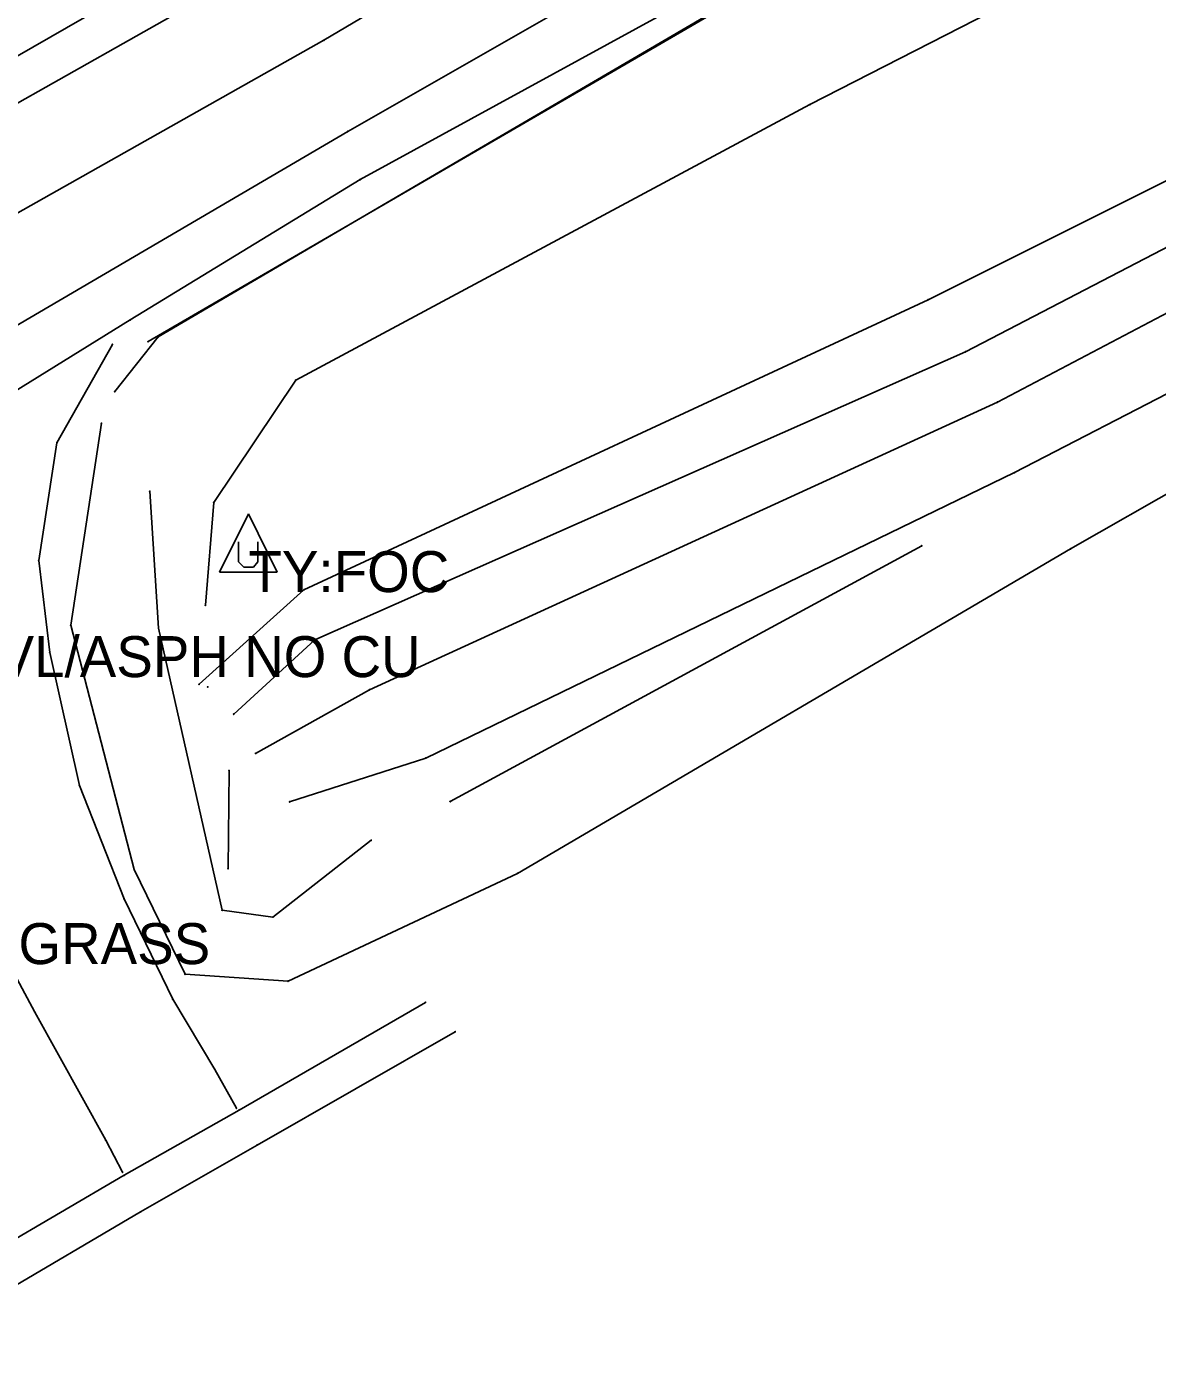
# Model space of a CAD drawing. Extents: x 1419505 to 1434054, y 1956910 to 1968644.
# Drawn here: x 1423167.1 to 1423305.2, y 1958878 to 1959040 of the extents above; entities that cross this region are included whole.
import ezdxf

# ---------------------------------------------------------------- set-up
doc = ezdxf.new("R2010")
doc.units = 0
for name, color, linetype in [('S_BREAKLINE', 7, 'Continuous'), ('S_DITCHLINE', 7, 'Continuous'), ('S_DRIVEWAY', 7, 'Continuous'), ('S_EDGE_PAVEMENT', 7, 'Continuous'), ('S_GRD_PT_SYM', 7, 'Continuous'), ('S_MSC_PT_SYM', 7, 'Continuous'), ('S_PAVEMENT_CROWN', 7, 'Continuous'), ('S_RAILROAD', 7, 'Continuous'), ('S_RDW_PT_SYM', 7, 'Continuous'), ('S_SHOULDER', 7, 'Continuous'), ('S_SURVEY_TEXT_ANNOT', 7, 'Continuous'), ('S_UTILITY_POLE', 7, 'Continuous'), ('S_UTILITY_POLE_ANNOT', 7, 'Continuous')]:
    doc.layers.add(name, color=color, linetype=linetype)

msp = doc.modelspace()

# ---------------------------------------------------------------- linework, layer by layer
at = {"layer": 'S_BREAKLINE'}
for p, q in [((1423338.2538, 1959069.1957), (1423262.7609, 1959030.5292)), ((1423352.9877, 1959044.6211), (1423277.1788, 1959006.6887)), ((1423254.8784, 1959043.9591), (1423181.9857, 1959001.5804)), ((1423211.1586, 1959018.5505), (1423249.766, 1959041.1529)), ((1423262.7609, 1959030.5292), (1423200.0178, 1958996.8931)), ((1423364.3604, 1959025.2919), (1423287.7345, 1958985.5943)), ((1423183.2267, 1959002.1714), (1423211.1586, 1959018.5505)), ((1423367.9047, 1959018.2304), (1423294.5749, 1958976.2907)), ((1423277.1788, 1959006.6887), (1423201.0049, 1958971.2974)), ((1423177.9094, 1958995.48), (1423183.2267, 1959002.1714)), ((1423200.0178, 1958996.8931), (1423189.9952, 1958981.9561)), ((1423172.5581, 1958966.9561), (1423176.3003, 1958991.6137)), ((1423287.7345, 1958985.5943), (1423215.8679, 1958950.7561)), ((1423183.2628, 1958966.6031), (1423182.1957, 1958983.3132)), ((1423189.9952, 1958981.9561), (1423188.9921, 1958969.4003)), ((1423218.8531, 1958945.4577), (1423276.4158, 1958976.6498)), ((1423294.5749, 1958976.2907), (1423227.0556, 1958936.6762)), ((1423201.0049, 1958971.2974), (1423188.2101, 1958959.7577)), ((1423180.2956, 1958937.1502), (1423172.5581, 1958966.9561)), ((1423191.0223, 1958932.1769), (1423183.2628, 1958966.6031)), ((1423215.8679, 1958950.7561), (1423199.2498, 1958945.4137)), ((1423209.2224, 1958940.7204), (1423197.2247, 1958931.3518)), ((1423186.492, 1958924.3684), (1423180.2956, 1958937.1502)), ((1423227.0556, 1958936.6762), (1423199.0668, 1958923.5173)), ((1423197.2247, 1958931.3518), (1423191.0223, 1958932.1769)), ((1423199.0668, 1958923.5173), (1423186.492, 1958924.3684))]:
    msp.add_line(p, q, dxfattribs=at)
at = {"layer": 'S_DITCHLINE'}
for p, q in [((1423356.0379, 1959038.9768), (1423281.7411, 1959000.3383)), ((1423359.5261, 1959033.1234), (1423285.6414, 1958994.2019)), ((1423281.7411, 1959000.3383), (1423202.345, 1958965.201)), ((1423285.6414, 1958994.2019), (1423208.9974, 1958959.0726)), ((1423202.345, 1958965.201), (1423192.4313, 1958956.1124)), ((1423208.9974, 1958959.0726), (1423195.1045, 1958951.3281)), ((1423191.7343, 1958937.2612), (1423191.8583, 1958949.223))]:
    msp.add_line(p, q, dxfattribs=at)
at = {"layer": 'S_DRIVEWAY'}
for p, q in [((1423170.857, 1958989.2406), (1423177.6244, 1959001.2403)), ((1423168.6408, 1958974.8786), (1423170.857, 1958989.2406)), ((1423169.9909, 1958963.6429), (1423168.6408, 1958974.8786)), ((1423173.6121, 1958947.3899), (1423169.9909, 1958963.6429)), ((1423179.0425, 1958933.557), (1423173.6121, 1958947.3899)), ((1423184.9859, 1958921.3232), (1423179.0425, 1958933.557)), ((1423162.9934, 1958929.3557), (1423168.1588, 1958919.7381)), ((1423190.1412, 1958912.7456), (1423184.9859, 1958921.3232)), ((1423168.1588, 1958919.7381), (1423176.8153, 1958904.1021)), ((1423192.7674, 1958908.0203), (1423190.1412, 1958912.7456)), ((1423176.8153, 1958904.1021), (1423178.8705, 1958900.2038))]:
    msp.add_line(p, q, dxfattribs=at)
at = {"layer": 'S_EDGE_PAVEMENT'}
for p, q in [((1423148.7845, 1959020.9336), (1423199.3688, 1959049.5305)), ((1423206.3462, 1959027.228), (1423244.2417, 1959048.8994)), ((1423159.6542, 1958999.8743), (1423206.3462, 1959027.228))]:
    msp.add_line(p, q, dxfattribs=at)
at = {"layer": 'S_GRD_PT_SYM'}
for points in [[(1423262.7609, 1959030.5292), (1423262.7609, 1959030.5792), (1423262.7609, 1959030.5292), (1423262.7109, 1959030.5292), (1423262.7609, 1959030.5292), (1423262.7609, 1959030.4792), (1423262.7609, 1959030.5292), (1423262.8109, 1959030.5292)], [(1423211.1586, 1959018.5505), (1423211.1586, 1959018.6005), (1423211.1586, 1959018.5505), (1423211.1086, 1959018.5505), (1423211.1586, 1959018.5505), (1423211.1586, 1959018.5005), (1423211.1586, 1959018.5505), (1423211.2086, 1959018.5505)], [(1423277.1788, 1959006.6887), (1423277.1788, 1959006.7387), (1423277.1788, 1959006.6887), (1423277.1288, 1959006.6887), (1423277.1788, 1959006.6887), (1423277.1788, 1959006.6387), (1423277.1788, 1959006.6887), (1423277.2288, 1959006.6887)], [(1423181.9857, 1959001.5804), (1423181.9857, 1959001.6304), (1423181.9857, 1959001.5804), (1423181.9357, 1959001.5804), (1423181.9857, 1959001.5804), (1423181.9857, 1959001.5304), (1423181.9857, 1959001.5804), (1423182.0357, 1959001.5804)], [(1423183.2267, 1959002.1714), (1423183.2267, 1959002.2214), (1423183.2267, 1959002.1714), (1423183.1767, 1959002.1714), (1423183.2267, 1959002.1714), (1423183.2267, 1959002.1214), (1423183.2267, 1959002.1714), (1423183.2767, 1959002.1714)], [(1423281.7411, 1959000.3383), (1423281.7411, 1959000.3883), (1423281.7411, 1959000.3383), (1423281.6911, 1959000.3383), (1423281.7411, 1959000.3383), (1423281.7411, 1959000.2883), (1423281.7411, 1959000.3383), (1423281.7911, 1959000.3383)], [(1423200.0178, 1958996.8931), (1423200.0178, 1958996.9431), (1423200.0178, 1958996.8931), (1423199.9678, 1958996.8931), (1423200.0178, 1958996.8931), (1423200.0178, 1958996.8431), (1423200.0178, 1958996.8931), (1423200.0678, 1958996.8931)], [(1423177.9094, 1958995.48), (1423177.9094, 1958995.53), (1423177.9094, 1958995.48), (1423177.8594, 1958995.48), (1423177.9094, 1958995.48), (1423177.9094, 1958995.43), (1423177.9094, 1958995.48), (1423177.9594, 1958995.48)], [(1423285.6414, 1958994.2019), (1423285.6414, 1958994.2519), (1423285.6414, 1958994.2019), (1423285.5914, 1958994.2019), (1423285.6414, 1958994.2019), (1423285.6414, 1958994.1519), (1423285.6414, 1958994.2019), (1423285.6914, 1958994.2019)], [(1423176.3003, 1958991.6137), (1423176.3003, 1958991.6637), (1423176.3003, 1958991.6137), (1423176.2503, 1958991.6137), (1423176.3003, 1958991.6137), (1423176.3003, 1958991.5637), (1423176.3003, 1958991.6137), (1423176.3503, 1958991.6137)], [(1423287.7345, 1958985.5943), (1423287.7345, 1958985.6443), (1423287.7345, 1958985.5943), (1423287.6845, 1958985.5943), (1423287.7345, 1958985.5943), (1423287.7345, 1958985.5443), (1423287.7345, 1958985.5943), (1423287.7845, 1958985.5943)], [(1423182.1957, 1958983.3132), (1423182.1957, 1958983.3632), (1423182.1957, 1958983.3132), (1423182.1457, 1958983.3132), (1423182.1957, 1958983.3132), (1423182.1957, 1958983.2632), (1423182.1957, 1958983.3132), (1423182.2457, 1958983.3132)], [(1423189.9952, 1958981.9561), (1423189.9952, 1958982.0061), (1423189.9952, 1958981.9561), (1423189.9452, 1958981.9561), (1423189.9952, 1958981.9561), (1423189.9952, 1958981.9061), (1423189.9952, 1958981.9561), (1423190.0452, 1958981.9561)], [(1423276.4158, 1958976.6498), (1423276.4158, 1958976.6998), (1423276.4158, 1958976.6498), (1423276.3658, 1958976.6498), (1423276.4158, 1958976.6498), (1423276.4158, 1958976.5998), (1423276.4158, 1958976.6498), (1423276.4658, 1958976.6498)], [(1423294.5749, 1958976.2907), (1423294.5749, 1958976.3407), (1423294.5749, 1958976.2907), (1423294.5249, 1958976.2907), (1423294.5749, 1958976.2907), (1423294.5749, 1958976.2407), (1423294.5749, 1958976.2907), (1423294.6249, 1958976.2907)], [(1423201.0049, 1958971.2974), (1423201.0049, 1958971.3474), (1423201.0049, 1958971.2974), (1423200.9549, 1958971.2974), (1423201.0049, 1958971.2974), (1423201.0049, 1958971.2474), (1423201.0049, 1958971.2974), (1423201.0549, 1958971.2974)], [(1423188.9921, 1958969.4003), (1423188.9921, 1958969.4503), (1423188.9921, 1958969.4003), (1423188.9421, 1958969.4003), (1423188.9921, 1958969.4003), (1423188.9921, 1958969.3503), (1423188.9921, 1958969.4003), (1423189.0421, 1958969.4003)], [(1423172.5581, 1958966.9561), (1423172.5581, 1958967.0061), (1423172.5581, 1958966.9561), (1423172.5081, 1958966.9561), (1423172.5581, 1958966.9561), (1423172.5581, 1958966.9061), (1423172.5581, 1958966.9561), (1423172.6081, 1958966.9561)], [(1423183.2628, 1958966.6031), (1423183.2628, 1958966.6531), (1423183.2628, 1958966.6031), (1423183.2128, 1958966.6031), (1423183.2628, 1958966.6031), (1423183.2628, 1958966.5531), (1423183.2628, 1958966.6031), (1423183.3128, 1958966.6031)], [(1423202.345, 1958965.201), (1423202.345, 1958965.251), (1423202.345, 1958965.201), (1423202.295, 1958965.201), (1423202.345, 1958965.201), (1423202.345, 1958965.151), (1423202.345, 1958965.201), (1423202.395, 1958965.201)], [(1423188.2101, 1958959.7577), (1423188.2101, 1958959.8077), (1423188.2101, 1958959.7577), (1423188.1601, 1958959.7577), (1423188.2101, 1958959.7577), (1423188.2101, 1958959.7077), (1423188.2101, 1958959.7577), (1423188.2601, 1958959.7577)], [(1423189.2581, 1958959.4276), (1423189.2581, 1958959.4776), (1423189.2581, 1958959.4276), (1423189.2081, 1958959.4276), (1423189.2581, 1958959.4276), (1423189.2581, 1958959.3776), (1423189.2581, 1958959.4276), (1423189.3081, 1958959.4276)], [(1423208.9974, 1958959.0726), (1423208.9974, 1958959.1226), (1423208.9974, 1958959.0726), (1423208.9474, 1958959.0726), (1423208.9974, 1958959.0726), (1423208.9974, 1958959.0226), (1423208.9974, 1958959.0726), (1423209.0474, 1958959.0726)], [(1423192.4313, 1958956.1124), (1423192.4313, 1958956.1624), (1423192.4313, 1958956.1124), (1423192.3813, 1958956.1124), (1423192.4313, 1958956.1124), (1423192.4313, 1958956.0624), (1423192.4313, 1958956.1124), (1423192.4813, 1958956.1124)], [(1423195.1045, 1958951.3281), (1423195.1045, 1958951.3781), (1423195.1045, 1958951.3281), (1423195.0545, 1958951.3281), (1423195.1045, 1958951.3281), (1423195.1045, 1958951.2781), (1423195.1045, 1958951.3281), (1423195.1545, 1958951.3281)], [(1423215.8679, 1958950.7561), (1423215.8679, 1958950.8061), (1423215.8679, 1958950.7561), (1423215.8179, 1958950.7561), (1423215.8679, 1958950.7561), (1423215.8679, 1958950.7061), (1423215.8679, 1958950.7561), (1423215.9179, 1958950.7561)], [(1423191.8583, 1958949.223), (1423191.8583, 1958949.273), (1423191.8583, 1958949.223), (1423191.8083, 1958949.223), (1423191.8583, 1958949.223), (1423191.8583, 1958949.173), (1423191.8583, 1958949.223), (1423191.9083, 1958949.223)], [(1423199.2498, 1958945.4137), (1423199.2498, 1958945.4637), (1423199.2498, 1958945.4137), (1423199.1998, 1958945.4137), (1423199.2498, 1958945.4137), (1423199.2498, 1958945.3637), (1423199.2498, 1958945.4137), (1423199.2998, 1958945.4137)], [(1423218.8531, 1958945.4577), (1423218.8531, 1958945.5077), (1423218.8531, 1958945.4577), (1423218.8031, 1958945.4577), (1423218.8531, 1958945.4577), (1423218.8531, 1958945.4077), (1423218.8531, 1958945.4577), (1423218.9031, 1958945.4577)], [(1423209.2224, 1958940.7204), (1423209.2224, 1958940.7704), (1423209.2224, 1958940.7204), (1423209.1724, 1958940.7204), (1423209.2224, 1958940.7204), (1423209.2224, 1958940.6704), (1423209.2224, 1958940.7204), (1423209.2724, 1958940.7204)], [(1423180.2956, 1958937.1502), (1423180.2956, 1958937.2002), (1423180.2956, 1958937.1502), (1423180.2456, 1958937.1502), (1423180.2956, 1958937.1502), (1423180.2956, 1958937.1002), (1423180.2956, 1958937.1502), (1423180.3456, 1958937.1502)], [(1423191.7343, 1958937.2612), (1423191.7343, 1958937.3112), (1423191.7343, 1958937.2612), (1423191.6843, 1958937.2612), (1423191.7343, 1958937.2612), (1423191.7343, 1958937.2112), (1423191.7343, 1958937.2612), (1423191.7843, 1958937.2612)], [(1423227.0556, 1958936.6762), (1423227.0556, 1958936.7262), (1423227.0556, 1958936.6762), (1423227.0056, 1958936.6762), (1423227.0556, 1958936.6762), (1423227.0556, 1958936.6262), (1423227.0556, 1958936.6762), (1423227.1056, 1958936.6762)], [(1423191.0223, 1958932.1769), (1423191.0223, 1958932.2269), (1423191.0223, 1958932.1769), (1423190.9723, 1958932.1769), (1423191.0223, 1958932.1769), (1423191.0223, 1958932.1269), (1423191.0223, 1958932.1769), (1423191.0723, 1958932.1769)], [(1423197.2247, 1958931.3518), (1423197.2247, 1958931.4018), (1423197.2247, 1958931.3518), (1423197.1747, 1958931.3518), (1423197.2247, 1958931.3518), (1423197.2247, 1958931.3018), (1423197.2247, 1958931.3518), (1423197.2747, 1958931.3518)], [(1423186.492, 1958924.3684), (1423186.492, 1958924.4184), (1423186.492, 1958924.3684), (1423186.442, 1958924.3684), (1423186.492, 1958924.3684), (1423186.492, 1958924.3184), (1423186.492, 1958924.3684), (1423186.542, 1958924.3684)], [(1423199.0668, 1958923.5173), (1423199.0668, 1958923.5673), (1423199.0668, 1958923.5173), (1423199.0168, 1958923.5173), (1423199.0668, 1958923.5173), (1423199.0668, 1958923.4673), (1423199.0668, 1958923.5173), (1423199.1168, 1958923.5173)]]:
    msp.add_lwpolyline(points, dxfattribs=at)
at = {"layer": 'S_MSC_PT_SYM'}
for points in [[(1423215.8289, 1958920.9302), (1423215.8289, 1958920.9802), (1423215.8289, 1958920.9302), (1423215.7789, 1958920.9302), (1423215.8289, 1958920.9302), (1423215.8289, 1958920.8802), (1423215.8289, 1958920.9302), (1423215.8789, 1958920.9302)], [(1423219.4731, 1958917.3489), (1423219.4731, 1958917.3989), (1423219.4731, 1958917.3489), (1423219.4231, 1958917.3489), (1423219.4731, 1958917.3489), (1423219.4731, 1958917.2989), (1423219.4731, 1958917.3489), (1423219.5231, 1958917.3489)], [(1423193.0954, 1958907.7863), (1423193.0954, 1958907.8363), (1423193.0954, 1958907.7863), (1423193.0454, 1958907.7863), (1423193.0954, 1958907.7863), (1423193.0954, 1958907.7363), (1423193.0954, 1958907.7863), (1423193.1454, 1958907.7863)], [(1423195.2735, 1958903.516), (1423195.2735, 1958903.566), (1423195.2735, 1958903.516), (1423195.2235, 1958903.516), (1423195.2735, 1958903.516), (1423195.2735, 1958903.466), (1423195.2735, 1958903.516), (1423195.3235, 1958903.516)], [(1423179.0755, 1958899.8298), (1423179.0755, 1958899.8798), (1423179.0755, 1958899.8298), (1423179.0255, 1958899.8298), (1423179.0755, 1958899.8298), (1423179.0755, 1958899.7798), (1423179.0755, 1958899.8298), (1423179.1255, 1958899.8298)], [(1423181.0466, 1958895.3505), (1423181.0466, 1958895.4005), (1423181.0466, 1958895.3505), (1423180.9966, 1958895.3505), (1423181.0466, 1958895.3505), (1423181.0466, 1958895.3005), (1423181.0466, 1958895.3505), (1423181.0966, 1958895.3505)]]:
    msp.add_lwpolyline(points, dxfattribs=at)
at = {"layer": 'S_PAVEMENT_CROWN'}
for p, q in [((1423203.4401, 1959038.3777), (1423238.5113, 1959059.2191)), ((1423154.6389, 1959010.87), (1423203.4401, 1959038.3777))]:
    msp.add_line(p, q, dxfattribs=at)
at = {"layer": 'S_RAILROAD'}
for p, q in [((1423193.0954, 1958907.7863), (1423215.8289, 1958920.9302)), ((1423219.4731, 1958917.3489), (1423195.2735, 1958903.516)), ((1423179.0755, 1958899.8298), (1423193.0954, 1958907.7863)), ((1423195.2735, 1958903.516), (1423181.0466, 1958895.3505)), ((1423148.9815, 1958882.2677), (1423179.0755, 1958899.8298)), ((1423181.0466, 1958895.3505), (1423151.4147, 1958877.9584))]:
    msp.add_line(p, q, dxfattribs=at)
at = {"layer": 'S_RDW_PT_SYM'}
for points in [[(1423203.4401, 1959038.3777), (1423203.4401, 1959038.4277), (1423203.4401, 1959038.3777), (1423203.3901, 1959038.3777), (1423203.4401, 1959038.3777), (1423203.4401, 1959038.3277), (1423203.4401, 1959038.3777), (1423203.4901, 1959038.3777)], [(1423206.3462, 1959027.228), (1423206.3462, 1959027.278), (1423206.3462, 1959027.228), (1423206.2962, 1959027.228), (1423206.3462, 1959027.228), (1423206.3462, 1959027.178), (1423206.3462, 1959027.228), (1423206.3962, 1959027.228)], [(1423207.8713, 1959021.3746), (1423207.8713, 1959021.4246), (1423207.8713, 1959021.3746), (1423207.8213, 1959021.3746), (1423207.8713, 1959021.3746), (1423207.8713, 1959021.3246), (1423207.8713, 1959021.3746), (1423207.9213, 1959021.3746)], [(1423179.8085, 1959004.2275), (1423179.8085, 1959004.2775), (1423179.8085, 1959004.2275), (1423179.7585, 1959004.2275), (1423179.8085, 1959004.2275), (1423179.8085, 1959004.1775), (1423179.8085, 1959004.2275), (1423179.8585, 1959004.2275)], [(1423177.6244, 1959001.2403), (1423177.6244, 1959001.2903), (1423177.6244, 1959001.2403), (1423177.5744, 1959001.2403), (1423177.6244, 1959001.2403), (1423177.6244, 1959001.1903), (1423177.6244, 1959001.2403), (1423177.6744, 1959001.2403)], [(1423170.857, 1958989.2406), (1423170.857, 1958989.2906), (1423170.857, 1958989.2406), (1423170.807, 1958989.2406), (1423170.857, 1958989.2406), (1423170.857, 1958989.1906), (1423170.857, 1958989.2406), (1423170.907, 1958989.2406)], [(1423168.6408, 1958974.8786), (1423168.6408, 1958974.9286), (1423168.6408, 1958974.8786), (1423168.5908, 1958974.8786), (1423168.6408, 1958974.8786), (1423168.6408, 1958974.8286), (1423168.6408, 1958974.8786), (1423168.6908, 1958974.8786)], [(1423169.9909, 1958963.6429), (1423169.9909, 1958963.6929), (1423169.9909, 1958963.6429), (1423169.9409, 1958963.6429), (1423169.9909, 1958963.6429), (1423169.9909, 1958963.5929), (1423169.9909, 1958963.6429), (1423170.0409, 1958963.6429)], [(1423173.6121, 1958947.3899), (1423173.6121, 1958947.4399), (1423173.6121, 1958947.3899), (1423173.5621, 1958947.3899), (1423173.6121, 1958947.3899), (1423173.6121, 1958947.3399), (1423173.6121, 1958947.3899), (1423173.6621, 1958947.3899)], [(1423179.0425, 1958933.557), (1423179.0425, 1958933.607), (1423179.0425, 1958933.557), (1423178.9925, 1958933.557), (1423179.0425, 1958933.557), (1423179.0425, 1958933.507), (1423179.0425, 1958933.557), (1423179.0925, 1958933.557)], [(1423184.9859, 1958921.3232), (1423184.9859, 1958921.3732), (1423184.9859, 1958921.3232), (1423184.9359, 1958921.3232), (1423184.9859, 1958921.3232), (1423184.9859, 1958921.2732), (1423184.9859, 1958921.3232), (1423185.0359, 1958921.3232)], [(1423168.1588, 1958919.7381), (1423168.1588, 1958919.7881), (1423168.1588, 1958919.7381), (1423168.1088, 1958919.7381), (1423168.1588, 1958919.7381), (1423168.1588, 1958919.6881), (1423168.1588, 1958919.7381), (1423168.2088, 1958919.7381)], [(1423190.1412, 1958912.7456), (1423190.1412, 1958912.7956), (1423190.1412, 1958912.7456), (1423190.0912, 1958912.7456), (1423190.1412, 1958912.7456), (1423190.1412, 1958912.6956), (1423190.1412, 1958912.7456), (1423190.1912, 1958912.7456)], [(1423192.7674, 1958908.0203), (1423192.7674, 1958908.0703), (1423192.7674, 1958908.0203), (1423192.7174, 1958908.0203), (1423192.7674, 1958908.0203), (1423192.7674, 1958907.9703), (1423192.7674, 1958908.0203), (1423192.8174, 1958908.0203)], [(1423176.8153, 1958904.1021), (1423176.8153, 1958904.1521), (1423176.8153, 1958904.1021), (1423176.7653, 1958904.1021), (1423176.8153, 1958904.1021), (1423176.8153, 1958904.0521), (1423176.8153, 1958904.1021), (1423176.8653, 1958904.1021)], [(1423178.8705, 1958900.2038), (1423178.8705, 1958900.2538), (1423178.8705, 1958900.2038), (1423178.8205, 1958900.2038), (1423178.8705, 1958900.2038), (1423178.8705, 1958900.1538), (1423178.8705, 1958900.2038), (1423178.9205, 1958900.2038)]]:
    msp.add_lwpolyline(points, dxfattribs=at)
at = {"layer": 'S_SHOULDER'}
for p, q in [((1423146.4394, 1959025.1989), (1423179.2455, 1959044.0561)), ((1423207.8713, 1959021.3746), (1423248.0519, 1959043.3811)), ((1423179.8085, 1959004.2275), (1423207.8713, 1959021.3746)), ((1423162.6274, 1958993.5938), (1423179.8085, 1959004.2275))]:
    msp.add_line(p, q, dxfattribs=at)
at = {"layer": 'S_UTILITY_POLE'}
for p, q in [((1423194.2305, 1958980.5444), (1423190.7042, 1958973.4532)), ((1423194.2305, 1958980.5444), (1423197.718, 1958973.4532)), ((1423193.0292, 1958974.6932), (1423193.0292, 1958977.1344)), ((1423195.393, 1958977.1344), (1423195.393, 1958974.6932)), ((1423190.7042, 1958973.4532), (1423197.718, 1958973.4532)), ((1423193.6492, 1958974.0344), (1423193.0292, 1958974.6932)), ((1423194.8505, 1958974.0344), (1423193.6492, 1958974.0344)), ((1423195.393, 1958974.6932), (1423194.8505, 1958974.0344))]:
    msp.add_line(p, q, dxfattribs=at)

# ---------------------------------------------------------------- texts
at = {"layer": 'S_SURVEY_TEXT_ANNOT'}
for s, p in [('GRVL/ASPH NO CU', (1423153.5728, 1958960.632)), ('TALL WEEDS AND GRASS', (1423105.9678, 1958925.6018))]:
    msp.add_text(s, height=5, dxfattribs=at).set_placement(p)
at = {"layer": 'S_UTILITY_POLE_ANNOT'}
msp.add_text('TY:FOC', height=5, dxfattribs=at).set_placement((1423194.2305, 1958971.0107))

doc.saveas('drawing.dxf')
